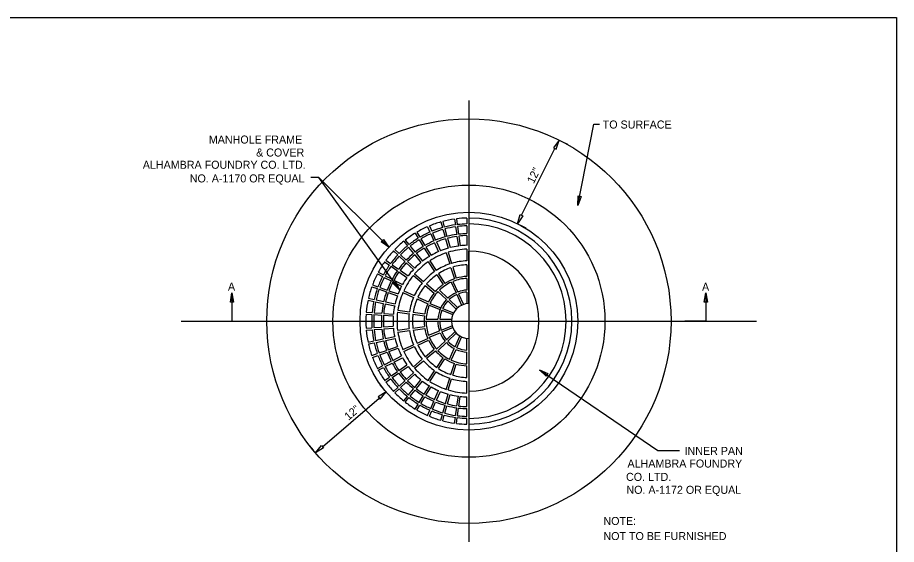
# Model space of a CAD drawing. Extents: x 6712067 to 6713867, y 1867712 to 1869162.
# Drawn here: x 6713208 to 6713867, y 1868767 to 1869162 of the extents above; entities that cross this region are included whole.
import ezdxf

# ---------------------------------------------------------------- set-up
doc = ezdxf.new("R2010")
doc.units = 0
for name, color, linetype in [('Control (1)', 7, 'Continuous'), ('Default', 7, 'Continuous'), ('G-MARK', 7, 'Continuous'), ('G-TEXT', 7, 'Continuous'), ('Misc CnstDet(22)', 7, 'Continuous')]:
    doc.layers.add(name, color=color, linetype=linetype)

# ---------------------------------------------------------------- blocks, each defined once
blk = doc.blocks.new('SC70480')
at = {"layer": 'Control (1)'}
blk.add_line((0, 0), (0, 0), dxfattribs=at)

msp = doc.modelspace()

# ---------------------------------------------------------------- linework, layer by layer
at = {"layer": 'Default'}
msp.add_lwpolyline([(6712066.89, 1869162.31), (6713866.89, 1869162.31), (6713866.89, 1867712.31), (6712066.89, 1867712.31)], close=True, dxfattribs=at)
at = {"layer": 'G-MARK'}
for p, q in [((6713585.79, 1869014.11), (6713610.74, 1869064.21)), ((6713494.41, 1868958.05), (6713433.62, 1869042.42)), ((6713584.85, 1869006.76), (6713588.94, 1869004.74)), ((6713482.72, 1868883.54), (6713479.76, 1868886.98)), ((6713436.52, 1868840.69), (6713479, 1868877.14))]:
    msp.add_line(p, q, dxfattribs=at)
for points in [[(6713628.01, 1869021.53), (6713640.04, 1869082.51), (6713644.31, 1869082.51)], [(6713486.27, 1868990.11), (6713433.62, 1869042.42), (6713427.83, 1869042.42)], [(6713368.57, 1868956.1), (6713368.57, 1868934.78), (6713384.46, 1868934.78)], [(6713723.97, 1868956.1), (6713723.97, 1868934.78), (6713708.09, 1868934.78)], [(6713599.16, 1868898.4), (6713687.84, 1868837.86), (6713704.3, 1868837.86)]]:
    msp.add_lwpolyline(points, dxfattribs=at)
at = {"layer": 'G-TEXT'}
for points in [[(6713609.68, 1869064.74), (6713611.77, 1869063.68), (6713613.86, 1869070.48)], [(6713630.49, 1869028.17), (6713628.01, 1869021.53), (6713628.22, 1869028.6)], [(6713584.74, 1869014.64), (6713586.83, 1869013.6), (6713582.67, 1869007.84)], [(6713482.11, 1868995.87), (6713486.27, 1868990.11), (6713480.48, 1868994.2)], [(6713491.27, 1868964.41), (6713494.41, 1868958.05), (6713489.36, 1868963.05)], [(6713367.4, 1868949.12), (6713368.57, 1868956.1), (6713369.72, 1868949.12)], [(6713722.8, 1868949.12), (6713723.97, 1868956.1), (6713725.14, 1868949.12)], [(6713604.28, 1868893.51), (6713599.16, 1868898.4), (6713605.59, 1868895.44)], [(6713478.24, 1868878.01), (6713479.76, 1868876.24), (6713484.33, 1868881.68)], [(6713435.76, 1868841.59), (6713437.28, 1868839.82), (6713431.22, 1868836.15)]]:
    msp.add_lwpolyline(points, close=True, dxfattribs=at)
at = {"layer": 'Misc CnstDet(22)'}
for p, q in [((6713546.26, 1869100.16), (6713546.26, 1868769.42)), ((6713613.86, 1869070.48), (6713613.86, 1869070.48)), ((6713613.86, 1869070.48), (6713613.86, 1869070.48)), ((6713616.04, 1869069.37), (6713620.1, 1869067.35)), ((6713525.21, 1869009.12), (6713526.41, 1869004.89)), ((6713526.64, 1869009.48), (6713527.83, 1869005.28)), ((6713535.52, 1869011.27), (6713536.12, 1869006.96)), ((6713536.96, 1869011.46), (6713537.56, 1869007.14)), ((6713544.81, 1869012.01), (6713544.81, 1869007.65)), ((6713546.26, 1869012.03), (6713546.26, 1869007.65)), ((6713582.67, 1869007.84), (6713582.67, 1869007.84)), ((6713507.24, 1869001.45), (6713509.52, 1868997.71)), ((6713515.32, 1869005.56), (6713517.07, 1869001.54)), ((6713516.65, 1869006.13), (6713518.42, 1869002.12)), ((6713526.82, 1869003.49), (6713528.4, 1868997.89)), ((6713528.22, 1869003.88), (6713529.8, 1868998.26)), ((6713536.32, 1869005.51), (6713537.15, 1868999.73)), ((6713537.77, 1869005.7), (6713538.59, 1868999.91)), ((6713544.81, 1869006.18), (6713544.81, 1869000.35)), ((6713498.54, 1868995.53), (6713501.32, 1868992.13)), ((6713505.98, 1869000.69), (6713508.28, 1868996.97)), ((6713509.03, 1868995.71), (6713512.06, 1868990.76)), ((6713510.27, 1868996.47), (6713513.33, 1868991.49)), ((6713517.66, 1869000.21), (6713519.98, 1868994.89)), ((6713518.99, 1869000.78), (6713521.34, 1868995.44)), ((6713528.79, 1868996.49), (6713530.79, 1868989.47)), ((6713530.19, 1868996.86), (6713532.19, 1868989.86)), ((6713537.33, 1868998.28), (6713538.36, 1868991.08)), ((6713538.78, 1868998.47), (6713539.81, 1868991.26)), ((6713544.81, 1868998.9), (6713544.81, 1868991.6)), ((6713490.74, 1868988.48), (6713493.93, 1868985.5)), ((6713497.4, 1868994.61), (6713500.17, 1868991.24)), ((6713501.09, 1868990.09), (6713504.79, 1868985.59)), ((6713502.24, 1868991.01), (6713505.91, 1868986.49)), ((6713512.82, 1868989.52), (6713516.63, 1868983.3)), ((6713514.08, 1868990.25), (6713517.89, 1868984.03)), ((6713520.58, 1868993.53), (6713523.49, 1868986.85)), ((6713521.91, 1868994.11), (6713524.85, 1868987.43)), ((6713544.81, 1868988.69), (6713544.81, 1868979.95)), ((6713489.73, 1868987.43), (6713492.92, 1868984.44)), ((6713494, 1868983.46), (6713498.27, 1868979.49)), ((6713495.01, 1868984.51), (6713499.28, 1868980.54)), ((6713505.71, 1868984.44), (6713510.32, 1868978.82)), ((6713506.85, 1868985.36), (6713511.44, 1868979.72)), ((6713529.23, 1868985.96), (6713531.89, 1868977.63)), ((6713530.63, 1868986.39), (6713533.27, 1868978.06)), ((6713546.26, 1868947.91), (6713546.26, 1868987.24)), ((6713483.1, 1868979.26), (6713486.68, 1868976.73)), ((6713483.95, 1868980.43), (6713487.53, 1868977.93)), ((6713487.87, 1868975.88), (6713492.65, 1868972.53)), ((6713488.72, 1868977.08), (6713493.5, 1868973.73)), ((6713499.33, 1868978.48), (6713504.67, 1868973.52)), ((6713500.34, 1868979.53), (6713505.68, 1868974.57)), ((6713515.74, 1868979.23), (6713520.58, 1868971.96)), ((6713516.95, 1868980.04), (6713521.79, 1868972.76)), ((6713534.16, 1868975.29), (6713536.8, 1868966.95)), ((6713544.81, 1868977.03), (6713544.81, 1868968.29)), ((6713477.66, 1868970.26), (6713481.54, 1868968.24)), ((6713478.33, 1868971.55), (6713482.2, 1868969.53)), ((6713483.51, 1868968.86), (6713488.7, 1868966.2)), ((6713493.84, 1868971.71), (6713499.78, 1868967.51)), ((6713494.69, 1868972.88), (6713500.63, 1868968.68)), ((6713504.63, 1868969.04), (6713511.31, 1868963.4)), ((6713505.57, 1868970.15), (6713512.25, 1868964.5)), ((6713522.21, 1868969.53), (6713527.05, 1868962.25)), ((6713523.42, 1868970.35), (6713528.27, 1868963.08)), ((6713532.76, 1868974.85), (6713535.43, 1868966.5)), ((6713473.96, 1868961.97), (6713478.1, 1868960.51)), ((6713482.82, 1868967.57), (6713488.01, 1868964.91)), ((6713489.3, 1868964.22), (6713495.77, 1868960.9)), ((6713489.98, 1868965.51), (6713496.46, 1868962.18)), ((6713514.47, 1868962.62), (6713521.15, 1868956.97)), ((6713532.99, 1868963.97), (6713536.62, 1868956.01)), ((6713534.33, 1868964.55), (6713537.95, 1868956.58)), ((6713544.81, 1868966.82), (6713544.81, 1868958.05)), ((6713473.46, 1868960.6), (6713477.59, 1868959.15)), ((6713478.97, 1868958.65), (6713484.45, 1868956.7)), ((6713479.47, 1868960.02), (6713484.96, 1868958.07)), ((6713485.83, 1868956.21), (6713492.69, 1868953.78)), ((6713486.33, 1868957.59), (6713493.2, 1868955.16)), ((6713496.75, 1868956.17), (6713504.74, 1868952.59)), ((6713497.35, 1868957.5), (6713505.34, 1868953.92)), ((6713513.53, 1868961.52), (6713520.21, 1868955.87)), ((6713523.08, 1868956.95), (6713529.41, 1868950.89)), ((6713524.11, 1868957.96), (6713530.45, 1868951.92)), ((6713538.57, 1868955.25), (6713542.2, 1868947.26)), ((6713544.81, 1868956.6), (6713544.81, 1868947.81)), ((6713470.64, 1868950.48), (6713474.91, 1868949.58)), ((6713470.93, 1868951.9), (6713475.23, 1868951)), ((6713476.35, 1868949.28), (6713482.04, 1868948.11)), ((6713476.65, 1868950.71), (6713482.36, 1868949.54)), ((6713483.79, 1868949.24), (6713490.93, 1868947.74)), ((6713507.4, 1868951.39), (6713515.39, 1868947.81)), ((6713508, 1868952.73), (6713515.99, 1868949.14)), ((6713530.47, 1868949.88), (6713536.78, 1868943.84)), ((6713531.5, 1868950.91), (6713537.86, 1868944.85)), ((6713537.22, 1868954.68), (6713540.84, 1868946.74)), ((6713483.47, 1868947.81), (6713490.6, 1868946.32)), ((6713492.99, 1868943.04), (6713501.64, 1868941.82)), ((6713516.52, 1868946.71), (6713524.62, 1868943.48)), ((6713517.09, 1868948.07), (6713525.21, 1868944.81)), ((6713525.97, 1868942.93), (6713534.1, 1868939.67)), ((6713526.57, 1868944.26), (6713534.72, 1868941)), ((6713469.21, 1868940.06), (6713473.57, 1868939.76)), ((6713469.33, 1868941.5), (6713473.69, 1868941.2)), ((6713475.02, 1868939.64), (6713480.83, 1868939.25)), ((6713475.13, 1868941.11), (6713480.94, 1868940.7)), ((6713482.3, 1868939.16), (6713489.57, 1868938.66)), ((6713482.41, 1868940.61), (6713489.69, 1868940.1)), ((6713492.78, 1868941.62), (6713501.44, 1868940.38)), ((6713504.33, 1868939.99), (6713512.98, 1868938.75)), ((6713504.54, 1868941.41), (6713513.19, 1868940.19)), ((6713514.24, 1868936.25), (6713522.99, 1868936.25)), ((6713524.46, 1868936.25), (6713533.22, 1868936.25)), ((6713330.47, 1868934.78), (6713762.07, 1868934.78)), ((6713469.21, 1868929.52), (6713473.57, 1868929.82)), ((6713475.02, 1868929.93), (6713480.83, 1868930.33)), ((6713475.13, 1868928.47), (6713480.94, 1868928.88)), ((6713482.3, 1868930.42), (6713489.57, 1868930.92)), ((6713482.41, 1868928.97), (6713489.69, 1868929.45)), ((6713492.78, 1868927.96), (6713501.44, 1868929.2)), ((6713504.33, 1868929.59), (6713512.98, 1868930.83)), ((6713504.54, 1868928.14), (6713513.19, 1868929.38)), ((6713514.2, 1868934.78), (6713522.94, 1868934.78)), ((6713524.41, 1868934.78), (6713533.16, 1868934.78)), ((6713525.49, 1868928.03), (6713533.61, 1868931.29)), ((6713525.97, 1868926.65), (6713534.1, 1868929.91)), ((6713469.33, 1868928.08), (6713473.69, 1868928.37)), ((6713483.47, 1868921.76), (6713490.6, 1868923.26)), ((6713492.99, 1868926.52), (6713501.64, 1868927.75)), ((6713515.99, 1868924.22), (6713524.11, 1868927.48)), ((6713516.52, 1868922.87), (6713524.62, 1868926.1)), ((6713529.48, 1868920.78), (6713535.84, 1868926.84)), ((6713530.47, 1868919.68), (6713536.78, 1868925.73)), ((6713535.91, 1868915.54), (6713539.54, 1868923.53)), ((6713537.22, 1868914.88), (6713540.84, 1868922.84)), ((6713470.64, 1868919.1), (6713474.91, 1868920)), ((6713470.93, 1868917.68), (6713475.23, 1868918.57)), ((6713476.35, 1868920.3), (6713482.04, 1868921.47)), ((6713476.65, 1868918.87), (6713482.36, 1868920.04)), ((6713483.79, 1868920.34), (6713490.93, 1868921.83)), ((6713485.83, 1868913.36), (6713492.69, 1868915.8)), ((6713496.75, 1868913.41), (6713504.74, 1868916.99)), ((6713497.35, 1868912.08), (6713505.34, 1868915.66)), ((6713507.4, 1868918.18), (6713515.39, 1868921.76)), ((6713508, 1868916.85), (6713515.99, 1868920.43)), ((6713522.09, 1868913.71), (6713528.43, 1868919.77)), ((6713523.08, 1868912.63), (6713529.41, 1868918.69)), ((6713544.81, 1868912.97), (6713544.81, 1868921.74)), ((6713546.26, 1868921.67), (6713546.26, 1868882.31)), ((6713473.46, 1868908.98), (6713477.59, 1868910.43)), ((6713473.96, 1868907.6), (6713478.1, 1868909.07)), ((6713478.97, 1868910.93), (6713484.45, 1868912.86)), ((6713479.47, 1868909.55), (6713484.96, 1868911.51)), ((6713486.33, 1868911.99), (6713493.2, 1868914.42)), ((6713513.53, 1868908.06), (6713520.21, 1868913.71)), ((6713514.47, 1868906.96), (6713521.15, 1868912.61)), ((6713531.69, 1868906.23), (6713535.31, 1868914.21)), ((6713532.99, 1868905.61), (6713536.62, 1868913.57)), ((6713544.81, 1868902.76), (6713544.81, 1868911.51)), ((6713482.82, 1868902), (6713488.01, 1868904.67)), ((6713483.51, 1868900.72), (6713488.7, 1868903.38)), ((6713489.3, 1868905.35), (6713495.77, 1868908.68)), ((6713489.98, 1868904.05), (6713496.46, 1868907.4)), ((6713504.63, 1868900.53), (6713511.31, 1868906.18)), ((6713505.57, 1868899.43), (6713512.25, 1868905.08)), ((6713522.21, 1868900.03), (6713527.05, 1868907.31)), ((6713523.42, 1868899.23), (6713528.27, 1868906.5)), ((6713532.76, 1868894.73), (6713535.43, 1868903.06)), ((6713534.16, 1868894.29), (6713536.8, 1868902.62)), ((6713477.66, 1868899.32), (6713481.54, 1868901.34)), ((6713478.33, 1868898.03), (6713482.2, 1868900.03)), ((6713487.87, 1868893.67), (6713492.65, 1868897.05)), ((6713488.72, 1868892.5), (6713493.5, 1868895.85)), ((6713493.84, 1868897.87), (6713499.78, 1868902.07)), ((6713494.69, 1868896.7), (6713500.63, 1868900.88)), ((6713499.33, 1868891.1), (6713504.67, 1868896.06)), ((6713515.74, 1868890.34), (6713520.58, 1868897.62)), ((6713516.95, 1868889.54), (6713521.79, 1868896.82)), ((6713544.81, 1868892.55), (6713544.81, 1868901.29)), ((6713483.1, 1868890.32), (6713486.68, 1868892.85)), ((6713483.95, 1868889.15), (6713487.53, 1868891.65)), ((6713494, 1868886.12), (6713498.27, 1868890.09)), ((6713500.34, 1868890.05), (6713505.68, 1868895)), ((6713505.71, 1868885.11), (6713510.32, 1868890.76)), ((6713506.85, 1868884.22), (6713511.44, 1868889.86)), ((6713529.23, 1868883.62), (6713531.89, 1868891.95)), ((6713530.63, 1868883.18), (6713533.27, 1868891.51)), ((6713544.81, 1868880.89), (6713544.81, 1868889.63)), ((6713489.73, 1868882.15), (6713492.92, 1868885.13)), ((6713490.74, 1868881.1), (6713493.93, 1868884.08)), ((6713495.01, 1868885.07), (6713499.28, 1868889.04)), ((6713501.09, 1868879.47), (6713504.79, 1868883.99)), ((6713502.24, 1868878.57), (6713505.91, 1868883.09)), ((6713512.82, 1868880.06), (6713516.63, 1868886.28)), ((6713514.08, 1868879.33), (6713517.89, 1868885.55)), ((6713520.58, 1868876.02), (6713523.49, 1868882.7)), ((6713484.33, 1868881.68), (6713484.33, 1868881.68)), ((6713484.33, 1868881.68), (6713484.33, 1868881.68)), ((6713497.4, 1868874.97), (6713500.17, 1868878.34)), ((6713498.54, 1868874.05), (6713501.32, 1868877.45)), ((6713509.03, 1868873.84), (6713512.06, 1868878.82)), ((6713510.27, 1868873.11), (6713513.33, 1868878.09)), ((6713521.91, 1868875.47), (6713524.85, 1868882.15)), ((6713528.79, 1868873.09), (6713530.79, 1868880.11)), ((6713530.19, 1868872.72), (6713532.19, 1868879.72)), ((6713537.33, 1868871.3), (6713538.36, 1868878.5)), ((6713538.78, 1868871.11), (6713539.81, 1868878.32)), ((6713544.81, 1868870.68), (6713544.81, 1868877.97)), ((6713505.98, 1868868.89), (6713508.28, 1868872.6)), ((6713507.24, 1868868.13), (6713509.52, 1868871.87)), ((6713517.66, 1868869.37), (6713519.98, 1868874.69)), ((6713518.99, 1868868.79), (6713521.34, 1868874.14)), ((6713526.82, 1868866.09), (6713528.4, 1868871.69)), ((6713528.22, 1868865.7), (6713529.8, 1868871.3)), ((6713536.32, 1868864.07), (6713537.15, 1868869.85)), ((6713537.77, 1868863.88), (6713538.59, 1868869.67)), ((6713515.32, 1868864.02), (6713517.07, 1868868.01)), ((6713516.65, 1868863.45), (6713518.42, 1868867.46)), ((6713525.21, 1868860.46), (6713526.41, 1868864.69)), ((6713526.64, 1868860.1), (6713527.83, 1868864.3)), ((6713544.81, 1868863.4), (6713544.81, 1868869.23)), ((6713535.52, 1868858.3), (6713536.12, 1868862.62)), ((6713536.96, 1868858.1), (6713537.56, 1868862.44)), ((6713544.81, 1868857.57), (6713544.81, 1868861.93)), ((6713546.26, 1868861.91), (6713546.26, 1868857.55)), ((6713429.61, 1868838), (6713426.65, 1868841.45)), ((6713431.22, 1868836.15), (6713431.22, 1868836.15))]:
    msp.add_line(p, q, dxfattribs=at)
for radius in [151.57, 102.02, 81.61]:
    msp.add_circle((6713546.27, 1868934.79), radius, dxfattribs=at)
for radius, start, end in [(77.24, 105.80925, 112.53768), (77.24, 97.99969, 104.72813), (77.24, 91.08112, 96.91858), (77.24, 270, 90), (77.24, 113.6188, 120.34724), (72.87, 113.6188, 120.28236), (72.87, 105.80925, 112.47281), (71.41, 105.80925, 112.44942), (72.87, 97.99969, 104.66326), (71.41, 97.99969, 104.63986), (72.87, 91.14599, 96.8537), (71.41, 91.16938, 96.83031), (72.87, 270, 90), (77.24, 121.42835, 128.15679), (72.87, 121.42835, 128.09191), (71.41, 121.42835, 128.06852), (71.41, 113.6188, 120.25897), (65.58, 113.6188, 120.15501), (65.58, 105.80925, 112.34546), (64.13, 105.80925, 112.31651), (65.58, 97.99969, 104.5359), (64.13, 97.99969, 104.50696), (65.58, 91.27334, 96.72635), (64.13, 91.30229, 96.6974), (77.24, 129.23791, 135.96634), (72.87, 129.23791, 135.90147), (71.41, 129.23791, 135.87807), (65.58, 121.42835, 127.96456), (64.13, 121.42835, 127.93562), (64.13, 113.6188, 120.12606), (56.84, 105.80925, 112.14952), (53.92, 91.54872, 106.85648), (56.84, 97.99969, 104.33996), (56.84, 91.46928, 96.53041), (77.24, 137.04746, 143.77589), (72.87, 137.04746, 143.71102), (71.41, 137.04746, 143.68763), (65.58, 129.23791, 135.77411), (64.13, 129.23791, 135.74517), (56.84, 121.42835, 127.76862), (53.92, 108.40506, 122.93853), (56.84, 113.6188, 119.95907), (52.47, 270, 90), (77.24, 144.85701, 151.58545), (72.87, 144.85701, 151.52057), (71.41, 144.85701, 151.49718), (65.58, 137.04746, 143.58367), (64.13, 137.04746, 143.55472), (53.92, 124.48711, 139.02058), (56.84, 129.23791, 135.57817), (45.18, 108.55494, 122.78866), (45.18, 91.84857, 106.70661), (42.26, 91.97611, 106.64287), (77.24, 152.66656, 159.395), (65.58, 144.85701, 151.39322), (64.13, 144.85701, 151.36428), (53.92, 140.56916, 155.10263), (56.84, 137.04746, 143.38773), (45.18, 124.63699, 138.87071), (42.26, 124.70073, 138.80697), (42.26, 108.61868, 122.72492), (72.87, 152.66656, 159.33013), (71.41, 152.66656, 159.30673), (65.58, 152.66656, 159.20277), (64.13, 152.66656, 159.17383), (56.84, 144.85701, 151.19728), (45.18, 140.71904, 154.95276), (33.52, 124.95848, 138.54922), (32.06, 114.45394, 133.69738), (33.52, 108.87643, 122.46717), (32.06, 92.60525, 111.84869), (33.52, 92.49191, 106.38511), (77.24, 160.47612, 167.20455), (72.87, 160.47612, 167.13968), (71.41, 160.47612, 167.11629), (65.58, 160.47612, 167.01233), (64.13, 160.47612, 166.98338), (53.92, 156.65122, 171.18469), (56.84, 152.66656, 159.00683), (42.26, 140.78278, 154.88902), (33.52, 141.04053, 154.63127), (32.06, 136.30263, 155.54606), (23.32, 114.45394, 132.71931), (23.32, 93.58332, 110.87062), (21.86, 93.82255, 110.63138), (77.24, 168.28567, 175.01411), (72.87, 168.28567, 174.94923), (71.41, 168.28567, 174.92584), (56.84, 160.47612, 166.81639), (45.18, 156.80109, 171.03481), (42.26, 156.86483, 170.97107), (23.32, 136.30263, 176.41668), (21.86, 136.30263, 154.32876), (21.86, 114.45394, 132.48007), (65.58, 168.28567, 174.82188), (64.13, 168.28567, 174.79293), (56.84, 168.28567, 174.62594), (33.52, 157.12258, 170.71332), (32.06, 158.15131, 177.39475), (21.86, 158.15131, 176.17745), (13.12, 90, 270), (77.24, 176.09522, 183.90478), (72.87, 176.09522, 183.90478), (71.41, 176.09522, 183.90478), (65.58, 176.09522, 183.90478), (64.13, 176.09522, 183.90478), (56.84, 176.09522, 183.90478), (53.92, 172.73327, 187.26674), (45.18, 172.88314, 187.11686), (42.26, 172.94688, 187.05312), (33.52, 173.20463, 186.79537), (65.58, 185.17812, 191.71433), (64.13, 185.20707, 191.71433), (56.84, 185.37406, 191.71433), (33.52, 189.28668, 202.87742), (32.06, 180, 199.24344), (23.32, 180, 198.26537), (21.86, 180, 198.02613), (77.24, 184.98589, 191.71433), (72.87, 185.05077, 191.71433), (71.41, 185.07416, 191.71433), (53.92, 188.81532, 203.34879), (45.18, 188.96519, 203.19891), (42.26, 189.02893, 203.13517), (32.06, 201.84869, 221.09212), (23.32, 201.84869, 220.11405), (21.86, 201.84869, 219.87482), (77.24, 192.79545, 199.52388), (72.87, 192.86032, 199.52388), (71.41, 192.88371, 199.52388), (65.58, 192.98768, 199.52388), (64.13, 193.01662, 199.52388), (56.84, 193.18361, 199.52388), (45.18, 205.04724, 219.28096), (42.26, 205.11098, 219.21722), (33.52, 205.36873, 218.95947), (23.32, 223.69737, 241.96274), (21.86, 223.69737, 241.72351), (72.87, 200.66987, 207.33344), (71.41, 200.69327, 207.33344), (65.58, 200.79723, 207.33344), (64.13, 200.82617, 207.33344), (56.84, 200.99317, 207.33344), (53.92, 204.89737, 219.43084), (33.52, 221.45078, 235.04152), (32.06, 223.69737, 242.94081), (23.32, 245.54606, 266.41668), (21.86, 245.54606, 266.17744), (77.24, 200.605, 207.33344), (65.58, 208.60678, 215.14299), (64.13, 208.63573, 215.14299), (56.84, 208.80272, 215.14299), (45.18, 221.12929, 235.36301), (42.26, 221.19303, 235.29927), (33.52, 237.53283, 251.12357), (32.06, 245.54606, 267.39475), (33.52, 253.61489, 267.50809), (77.24, 208.41455, 215.14299), (72.87, 208.47943, 215.14299), (71.41, 208.50282, 215.14299), (65.58, 216.41633, 222.95254), (64.13, 216.44528, 222.95254), (56.84, 216.61227, 222.95254), (53.92, 220.97942, 235.51289), (45.18, 237.21134, 251.44506), (42.26, 237.27508, 251.38132), (72.87, 216.28898, 222.95254), (71.41, 216.31237, 222.95254), (64.13, 224.25483, 230.76209), (56.84, 224.42183, 230.76209), (56.84, 232.23138, 238.57165), (53.92, 237.06147, 251.59494), (45.18, 253.29339, 268.15143), (42.26, 253.35713, 268.02389), (77.24, 216.22411, 222.95254), (72.87, 224.09853, 230.76209), (71.41, 224.12193, 230.76209), (65.58, 224.22589, 230.76209), (65.58, 232.03544, 238.57165), (64.13, 232.06438, 238.57165), (56.84, 240.04093, 246.3812), (53.92, 253.14352, 268.45128), (77.24, 224.03366, 230.76209), (72.87, 231.90809, 238.57165), (71.41, 231.93148, 238.57165), (65.58, 239.84499, 246.3812), (64.13, 239.87394, 246.3812), (56.84, 247.85048, 254.19075), (56.84, 255.66004, 262.00031), (56.84, 263.46959, 268.53072), (77.24, 231.84321, 238.57165), (72.87, 239.71764, 246.3812), (71.41, 239.74103, 246.3812), (65.58, 247.65454, 254.19075), (64.13, 247.68349, 254.19075), (65.58, 255.4641, 262.00031), (64.13, 255.49304, 262.00031), (65.58, 263.27365, 268.72666), (64.13, 263.30259, 268.69771), (77.24, 239.65276, 246.3812), (77.24, 247.46232, 254.19075), (72.87, 247.52719, 254.19075), (71.41, 247.55058, 254.19075), (72.87, 255.33675, 262.00031), (71.41, 255.36014, 262.00031), (71.41, 263.16969, 268.83062), (77.24, 255.27187, 262.00031), (77.24, 263.08142, 268.91888), (72.87, 263.1463, 268.85401)]:
    msp.add_arc((6713546.27, 1868934.79), radius, start, end, dxfattribs=at)

# ---------------------------------------------------------------- block references
at = {"layer": 'Misc CnstDet(22)', "xscale": 1377.06, "yscale": 1377.06}
for p in [(6713525.23, 1869009.13), (6713515.33, 1869005.57), (6713505.99, 1869000.7), (6713497.41, 1868994.62), (6713489.74, 1868987.44), (6713529.95, 1868986.2), (6713483.11, 1868979.27), (6713516.34, 1868979.66), (6713477.67, 1868970.27), (6713505.1, 1868969.61), (6713533.01, 1868963.98), (6713473.47, 1868960.61), (6713497.06, 1868956.85), (6713523.09, 1868956.96), (6713470.65, 1868950.49), (6713492.89, 1868942.34), (6713516.53, 1868946.72), (6713469.22, 1868940.07), (6713469.22, 1868929.53), (6713514.21, 1868934.79), (6713492.89, 1868927.26), (6713516.53, 1868922.88), (6713470.65, 1868919.11), (6713473.47, 1868908.99), (6713497.06, 1868912.76), (6713523.09, 1868912.64), (6713533.01, 1868905.62), (6713477.67, 1868899.33), (6713505.1, 1868900), (6713483.11, 1868890.33), (6713516.34, 1868889.94), (6713529.95, 1868883.4), (6713489.74, 1868882.16), (6713497.41, 1868874.98), (6713505.99, 1868868.9), (6713515.33, 1868864.03), (6713525.23, 1868860.47)]:
    msp.add_blockref('SC70480', p, dxfattribs=at)

# ---------------------------------------------------------------- texts
at = {"layer": 'Misc CnstDet(22)'}
for s, p in [('TO SURFACE', (6713646.63, 1869079.16)), ('MANHOLE FRAME', (6713351.25, 1869067.88)), ('& COVER', (6713386.68, 1869058.18)), ('ALHAMBRA FOUNDRY CO. LTD.', (6713301.72, 1869049)), ('NO. A-1170 OR EQUAL', (6713336.94, 1869038.76)), ('A', (6713365.58, 1868957.69)), ('A', (6713721.11, 1868957.55)), ('INNER PAN', (6713708, 1868834.53)), ('ALHAMBRA FOUNDRY', (6713665.21, 1868825.04)), ('CO. LTD.', (6713664.13, 1868815.05)), ('NO. A-1172 OR EQUAL', (6713664.4, 1868805.35)), ('NOTE:', (6713647.16, 1868782)), ('NOT TO BE FURNISHED', (6713647.16, 1868770.69))]:
    msp.add_text(s, height=6, dxfattribs=at).set_placement(p)
for rotation, p in [(63.52302, (6713594.84, 1869037.39)), (40.60806, (6713456.04, 1868860.08))]:
    msp.add_text('12"', height=6, rotation=rotation, dxfattribs=at).set_placement(p)

doc.saveas('drawing.dxf')
